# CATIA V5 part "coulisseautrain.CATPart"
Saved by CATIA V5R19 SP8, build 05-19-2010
Part number: coulisseautrain
Bounding box of the stored display mesh (mm): x -60 to 75, y -10 to 10, z -10 to 10
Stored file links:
  C:\Users\rcousturie\Desktop\EU_thinkMotion\iao\IAO_MMS_Groupe1\flamrini\Lamrini_projet_IAO2011\Lamrini_projet_IAO2011\projet_iao_traindatterrissage\projet_iao_traindatterrissage\coulisseautrain.CATPart
  C:\Users\rcousturie\Desktop\EU_thinkMotion\iao\IAO_MMS_Groupe1\flamrini\Lamrini_projet_IAO2011\Lamrini_projet_IAO2011\projet_iao_traindatterrissage\projet_iao_traindatterrissage\trainavion.CATProduct
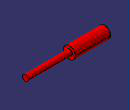
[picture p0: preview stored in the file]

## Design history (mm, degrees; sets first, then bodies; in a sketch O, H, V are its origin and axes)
Set1
  Sketch1 on yz-plane, origin (0, 0, 0), H (0, 1, 0), V (0, 0, 1)
    circle A1 centre (0, 0) radius 5
    point P1 (0, 0)
    reference projected point E1 (0, 0) from Point1
    radius A1 = 5
    coincidence: P1 E1
Set2
  Point1 "Pointb": linked copy from another document
Body1 (main body)
  Pad1: profile Sketch1, direction (1, 0, 0), length 75
  Sketch2 on start face of Pad1, origin (0, 0, 0), H (0, -1, 0), V (0, 0, 1)
    circle A1 centre (0, 0) radius 10
    point P1 (0, 0)
    reference projected point E1 (0, 0) from Point1
    radius A1 = 10
    coincidence: P1 E1
  Pad2: profile Sketch2, direction (-1, 0, 0), length 60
